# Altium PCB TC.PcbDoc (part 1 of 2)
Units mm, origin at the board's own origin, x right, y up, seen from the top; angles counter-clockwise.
Board outline 53.6 x 100 mm, 2 copper layers (Top Layer, Bottom Layer), stack 1.554 mm thick; 127 components, 95 nets, 328 pads, 171 vias.
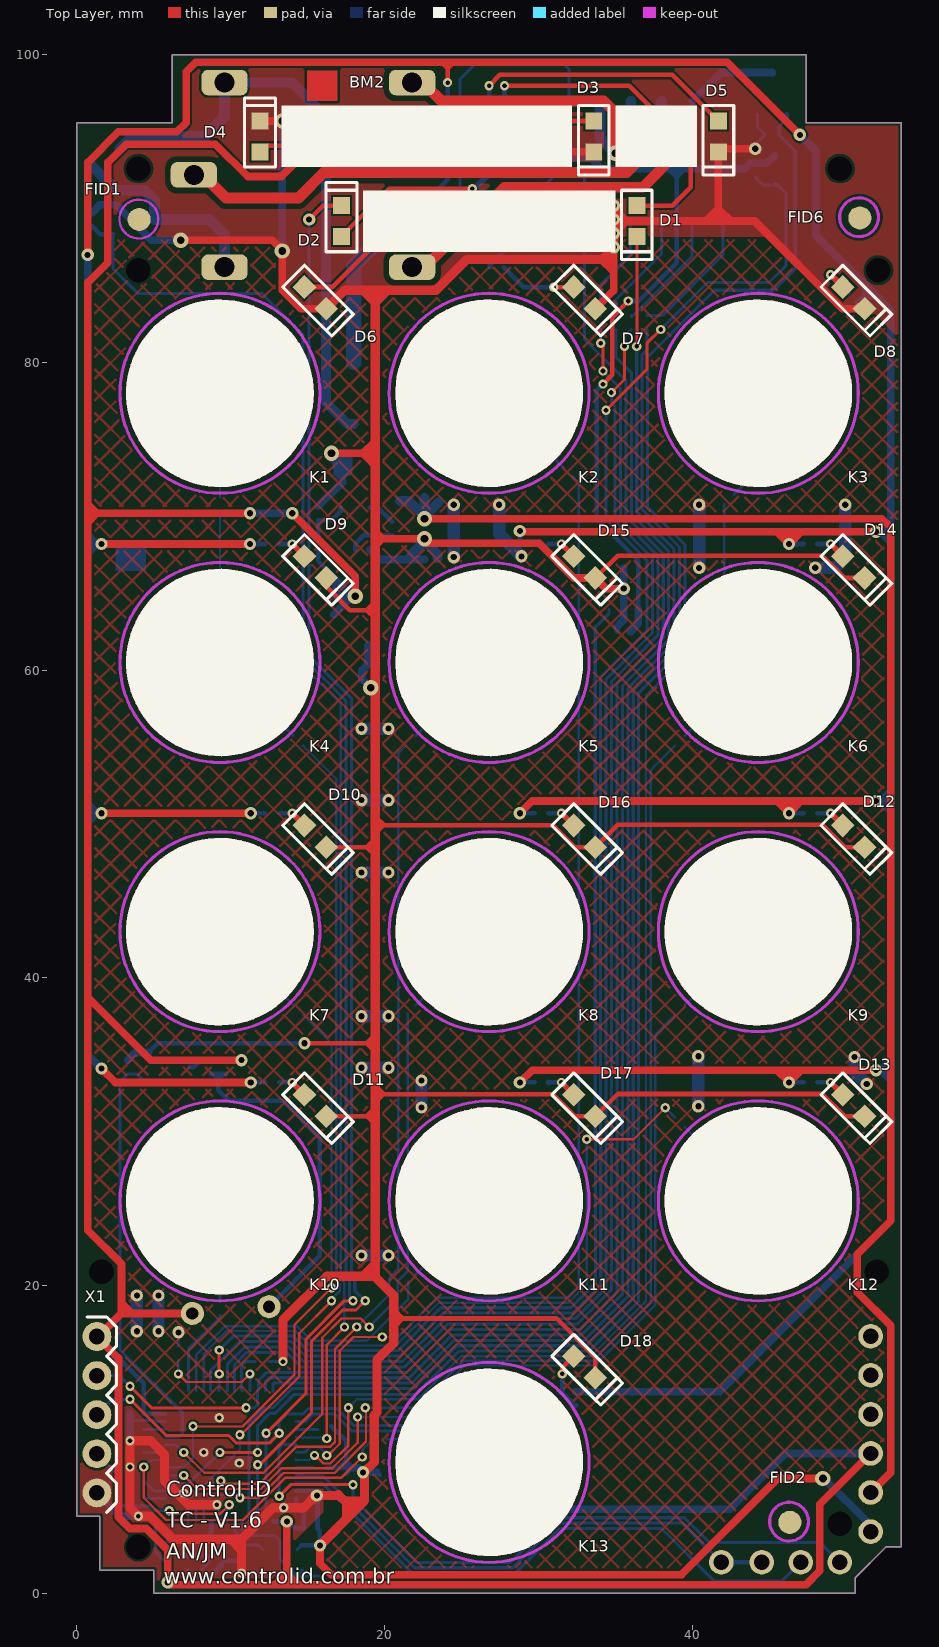
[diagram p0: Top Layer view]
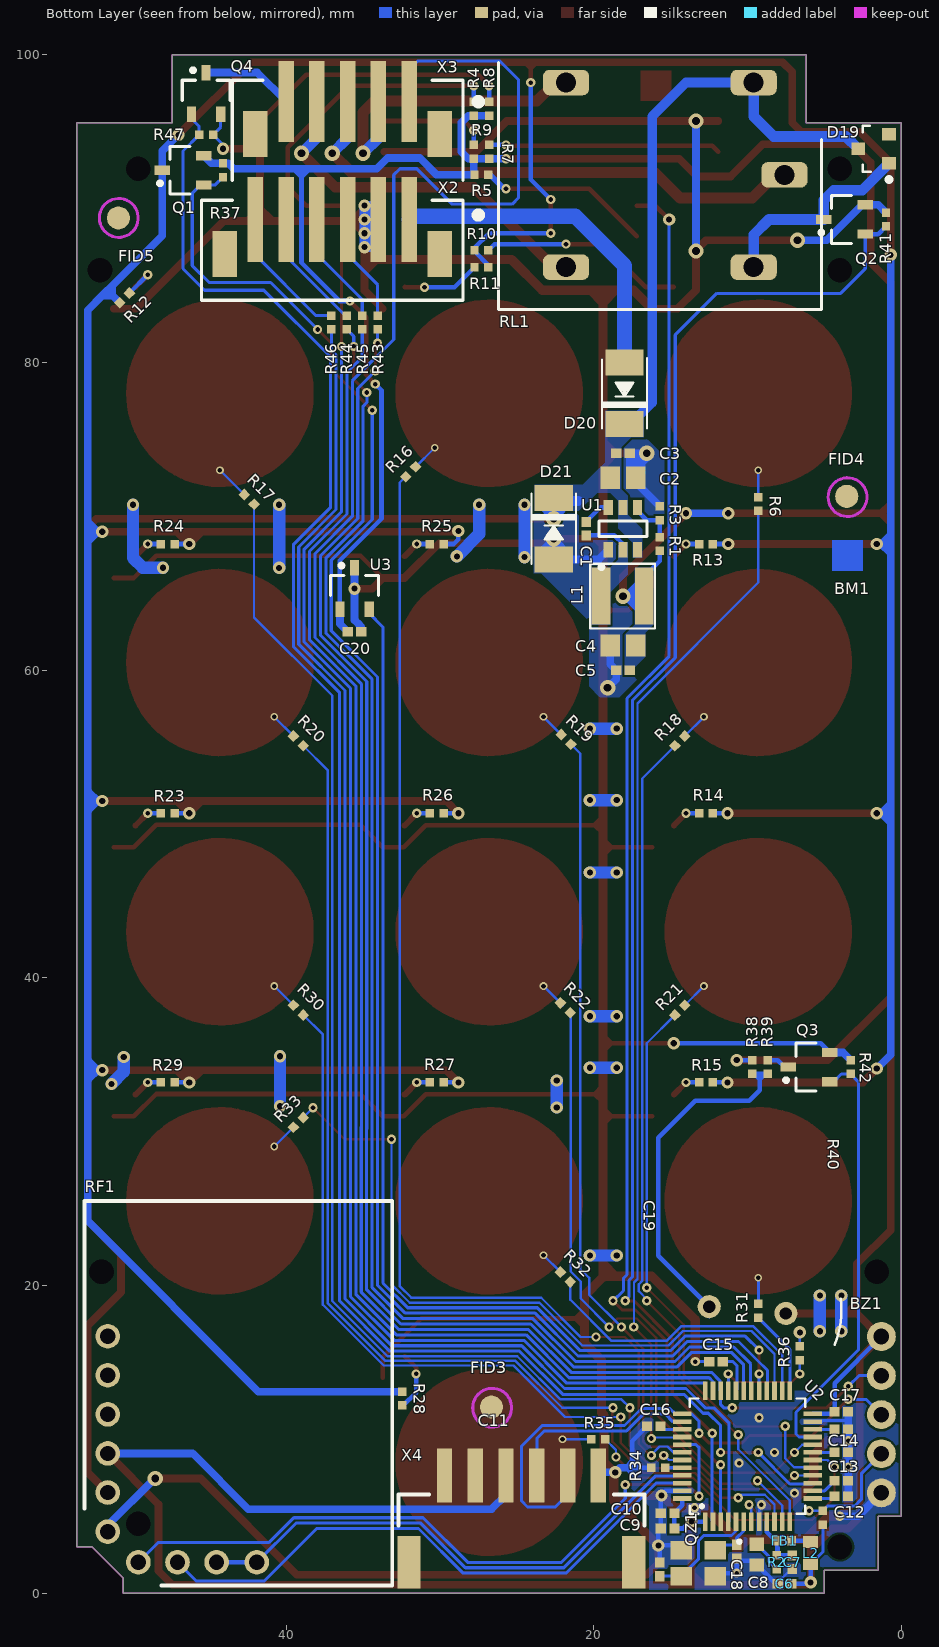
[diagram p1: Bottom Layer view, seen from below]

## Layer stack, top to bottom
Top Solder: solder mask 0.0102, Solder Resist, Dk 3.5
Top Layer: signal copper 0.0356
Dielectric 1: dielectric 1.4834, FR-4, Dk 4.8
Bottom Layer: signal copper 0.0356
Bottom Solder: solder mask 0.0102, Solder Resist, Dk 3.5

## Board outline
1.5,1.5 5,1.5 5,0 50.6,0 50.6,1 52.6,3 53.6,3 53.6,95.6 47.4,95.6 47.4,100 6.2,100 6.2,95.6 0,95.6 0,5 1.5,5

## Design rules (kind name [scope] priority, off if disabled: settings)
BoardOutlineClearance BoardOutlineClearance_1 [OnLayer('Top Overlay') or  OnLayer('Bottom Overlay')] p1: gap=0.051 ignorepadtopadclearanceinfootprint=FALSE
BoardOutlineClearance X1C [InComponent('X1')] p2 off: gap=0.102 ignorepadtopadclearanceinfootprint=FALSE
BoardOutlineClearance [All] p3: gap=0.152 ignorepadtopadclearanceinfootprint=FALSE
Clearance RELAY [InNet('COM_1') or InNet('NO_1') or InNet('NC_1')] p1: gap=0.254 ignorepadtopadclearanceinfootprint=FALSE except(0: Arc-Hole Track-Hole SMDPad-Hole THPad-Hole Via-Hole Fill-Hole Poly-Hole Region-Hole Text-Hole; 0.381: Arc-Poly Track-Poly SMDPad-Poly THPad-Poly Via-Poly Fill-Poly Poly-Poly)
Clearance X1 [InComponent('X1') vs OnLayer('Keep-Out Layer')] p2 off: gap=0.152 ignorepadtopadclearanceinfootprint=FALSE except(0: Arc-Hole Track-Hole SMDPad-Hole THPad-Hole Via-Hole Fill-Hole Poly-Hole Region-Hole Text-Hole)
Clearance U1Clear [InComponent('U1')] p3: gap=0.152 ignorepadtopadclearanceinfootprint=FALSE except(0: Arc-Hole Track-Hole SMDPad-Hole THPad-Hole Via-Hole Fill-Hole Poly-Hole Region-Hole Text-Hole)
Clearance [All] p4: gap=0.152 ignorepadtopadclearanceinfootprint=FALSE except(0: Arc-Hole Track-Hole SMDPad-Hole THPad-Hole Via-Hole Fill-Hole Poly-Hole Region-Hole Text-Hole)
ComponentClearance ComponentClearance_1 [HasFootprint('CAPKEY - NEW') vs HasFootprint('LTST-S270TBKT')] p1: gap=0 collisioncheckmode=3 verticalgap=0 showdistances=TRUE
ComponentClearance BZ1 [InComponent('BZ1')] p2: gap=0 collisioncheckmode=3 verticalgap=0 showdistances=TRUE
ComponentClearance [All] p3: gap=0.254 collisioncheckmode=3 verticalgap=0.254 showdistances=FALSE
MinimumSolderMaskSliver U1 [InComponent('U1')] p1: minsoldermaskwidth=0.025
MinimumSolderMaskSliver [All] p2: minsoldermaskwidth=0.064
PolygonConnect [All] p1: connectstyle=Direct reliefconductorwidth=0.254 reliefentries=4 polygonreliefangle="90 Angle" airgapwidth=0.254
RoutingVias [All] p1: holewidth=0.4 width=0.8 viastyle="Through Hole" minholewidth=0.3 minwidth=0.6 maxholewidth=0.5 maxwidth=1
SilkToSilkClearance [All] p1: silktosilkclearance=0.025
SilkToSolderMaskClearance [IsPad] p1: minsilkscreentomaskgap=0.025 clearancetoexposedcopper=TRUE
SolderMaskExpansion [All] p1: expansion=0.102
Width [All] p1: maxlimit=1 minlimit=0.152 preferedwidth=0.8 minimp=50.000000 maximp=50.000000 favimp=50.000000
26 further rules are at their usual default settings.

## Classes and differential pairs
net class GROUP3: CAP_GROUP3_1 M_CAPKEY13_1
net class GROUP6: CAP_GROUP6_1
net class Line1: M_CAPKEY1_1 M_CAPKEY2_1 M_CAPKEY3_1
net class Line2: M_CAPKEY4_1 M_CAPKEY5_1 M_CAPKEY6_1
net class Line3: M_CAPKEY7_1 M_CAPKEY8_1 M_CAPKEY9_1
net class Line4: M_CAPKEY10_1 M_CAPKEY11_1 M_CAPKEY12_1
net class Line5: M_CAPKEY13_1

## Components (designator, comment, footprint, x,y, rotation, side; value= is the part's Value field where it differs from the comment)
BM1 "BADMARK" BADMARK 3.5,67.45 r180 bottom
BM2 "BADMARK" BADMARK 15.95,98 r0 top
BZ1 "Buzzer" Buzzer 10,18.4 r5 bottom locked
C1 "Cap0402" C0402 20.5,69.2 r90 bottom value=100n
C2 "Cap0805" C0805 18.1,72.5 r0 bottom value=10u
C3 "Cap0402" C0402 18.1,74.1 r0 bottom value=100n
C4 "Cap0805" C0805 18.1,61.6 r0 bottom value=10u
C5 "Cap0402" C0402 18.1,60 r180 bottom value=100n
C6 "Cap0402" C0402 7.6,0.6 r180 bottom value=100n
C7 "Cap0402" C0402 7.1,2 r90 bottom value=100n
C8 "Cap0603" C0603 9.4,2.5 r90 bottom value=4.7u
C9 "Cap0402" C0402 15.2,4.2 r180 bottom value=100n
C10 "Cap0402" C0402 15.2,5.2 r180 bottom value=100n
C11 "Cap0402" C0402 3.9,11.8 r0 bottom value=100n
C12 "Cap0402" C0402 3.9,6.3 r0 bottom value=22n
C13 "Cap0402" C0402 3.9,7.3 r0 bottom value=22n
C14 "Cap0402" C0402 3.9,9.15 r0 bottom value=22n
C15 "Cap0402" C0402 12.05,15.05 r180 bottom value=22n
C16 "Cap0402" C0402 16.1,10.85 r180 bottom value=22n
C17 "Cap0402" C0402 3.9,10.65 r0 bottom value=10n
C18 "Cap0402" C0402 10.7,2.7 r90 bottom value=18pF
C19 "Cap0402" C0402 15.7,1.54 r270 bottom value=18pF
C20 "Cap0402" C0402 35.55,62.5 r0 bottom value=100n
D1 "XZMDK87W" LTST-S270TBKT 36.4,89.2 r0 top locked
D2 "XZDGK87W" LTST-S270TBKT 17.2,89.2 r180 top locked
D3 "XZCWD87F" LTST-S270TBKT 33.6,94.7 r0 top locked
D4 "XZCWD87F" LTST-S270TBKT 11.9,94.7 r180 top locked
D5 "XZMDK87W" LTST-S270TBKT 41.7,94.7 r0 top locked
D6 "XZCBD87W" LTST-S270TBKT 15.5,84.2 r45 top locked
D7 "XZCBD87W" LTST-S270TBKT 33,84.2 r45 top locked
D8 "XZCBD87W" LTST-S270TBKT 50.5,84.2 r45 top locked
D9 "XZCBD87W" LTST-S270TBKT 15.5,66.7 r45 top locked
D10 "XZCBD87W" LTST-S270TBKT 15.5,49.2 r45 top locked
D11 "XZCBD87W" LTST-S270TBKT 15.5,31.7 r45 top locked
D12 "XZCBD87W" LTST-S270TBKT 50.5,49.2 r45 top locked
D13 "XZCBD87W" LTST-S270TBKT 50.5,31.7 r45 top locked
D14 "XZCBD87W" LTST-S270TBKT 50.5,66.7 r45 top locked
D15 "XZCBD87W" LTST-S270TBKT 33,66.7 r45 top locked
D16 "XZCBD87W" LTST-S270TBKT 33,49.2 r45 top locked
D17 "XZCBD87W" LTST-S270TBKT 33,31.7 r45 top locked
D18 "XZCBD87W" LTST-S270TBKT 33,14.7 r45 top locked
D19 "BAS16LT3G" BAS16LT3G 1.8,93.9 r90 bottom
D20 "B360A-13-F" SMA 18,78 r90 bottom
D21 "SMAJ14A" SMA 22.6,69.2 r270 bottom
FB1 "Ferrite Bead" FB0402 7.6,3.4 r0 bottom
FID1 "FIDUCIAL" FIDUCIAL-1p5X3 4.05,89.3 r0 top
FID2 "FIDUCIAL" FIDUCIAL-1p5X3 46.35,4.6 r90 top
FID3 "FIDUCIAL" FIDUCIAL-1p5X3 26.65,12.1 r90 bottom
FID4 "FIDUCIAL" FIDUCIAL-1p5X3 3.55,71.3 r90 bottom
FID5 "FIDUCIAL" FIDUCIAL-1p5X3 50.9,89.4 r90 bottom
FID6 "FIDUCIAL" FIDUCIAL-1p5X3 50.9,89.4 r90 top
K1 "CAP_KEY" "CAPKEY - NEW" 9.3,78 r90 top locked
K2 "CAP_KEY" "CAPKEY - NEW" 26.8,78 r135 top locked
K3 "CAP_KEY" "CAPKEY - NEW" 44.3,78 r90 top locked
K4 "CAP_KEY" "CAPKEY - NEW" 9.3,60.5 r135 top locked
K5 "CAP_KEY" "CAPKEY - NEW" 26.8,60.5 r45 top locked
K6 "CAP_KEY" "CAPKEY - NEW" 44.3,60.5 r45 top locked
K7 "CAP_KEY" "CAPKEY - NEW" 9.3,43 r135 top locked
K8 "CAP_KEY" "CAPKEY - NEW" 26.8,43 r45 top locked
K9 "CAP_KEY" "CAPKEY - NEW" 44.3,43 r45 top locked
K10 "CAP_KEY" "CAPKEY - NEW" 9.3,25.5 r90 top locked
K11 "CAP_KEY" "CAPKEY - NEW" 26.8,25.5 r45 top locked
K12 "CAP_KEY" "CAPKEY - NEW" 44.3,25.5 r315 top
K13 "CAP_KEY" "CAPKEY - NEW" 26.8,8.5 r342.5 top locked
L1 "Inductor" NRS4018T3R3MDGJ 18.1,64.8 r180 bottom value=3.3u
L2 "Inductor" L0603 5.9,2.6 r90 bottom value=10u
Q1 "MOSFET-P" SOT23-3 46.7,92.5 r0 bottom
Q2 "DMN3404" SOT23-3 3.7,89.3 r0 bottom
Q3 "DMN3404" SOT23-3 6,34.2 r0 bottom
Q4 "DMN3404" SOT23-3 45.2,97.5 r90 bottom
QZ1 "ABM8G-12.000MHZ-18-D2Y-T" ABM8G-12.000MHZ-18-D2Y-T 13.2,1.95 r180 bottom locked value=12.000MHZ
R1 "Res0402" R0402 15.7,68.2 r270 bottom value=33K
R2 "Res0402" R0402 8.1,2 r90 bottom value=1
R3 "Res0402" R0402 15.7,70.2 r270 bottom value=10K
R4 "Res0402" R0402 27.8,96.5 r90 bottom value=68
R5 "Res0402" R0402 27.3,92.2 r180 bottom value=10
R6 "Res0402" R0402 9.3,70.8 r90 bottom value=10K
R7 "Res0402" R0402 26.8,93.7 r270 bottom value=10
R8 "Res0402" R0402 26.8,96.5 r270 bottom value=68
R9 "Res0402" R0402 27.8,93.7 r270 bottom value=10
R10 "Res0402" R0402 27.3,87.3 r0 bottom value=10
R11 "Res0402" R0402 27.3,86.2 r180 bottom value=10
R12 "Res0402" R0402 50.5,84.2 r315 bottom value=10
R13 "Res0402" R0402 12.7,68.2 r180 bottom value=10
R14 "Res0402" R0402 12.7,50.7 r180 bottom value=10
R15 "Res0402" R0402 12.7,33.2 r180 bottom value=10
R16 "Res0402" R0402 31.9,72.9 r135 bottom value=10K
R17 "Res0402" R0402 42.4,71.1 r45 bottom value=10K
R18 "Res0402" R0402 14.4,55.4 r135 bottom value=10K
R19 "Res0402" R0402 21.8,55.5 r45 bottom value=10K
R20 "Res0402" R0402 39.2,55.4 r45 bottom value=10K
R21 "Res0402" R0402 14.4,37.9 r135 bottom value=10K
R22 "Res0402" R0402 21.85,38.05 r45 bottom value=10K
R23 "Res0402" R0402 47.7,50.7 r180 bottom value=10
R24 "Res0402" R0402 47.7,68.2 r180 bottom value=10
R25 "Res0402" R0402 30.2,68.2 r180 bottom value=10
R26 "Res0402" R0402 30.2,50.7 r180 bottom value=10
R27 "Res0402" R0402 30.2,33.2 r180 bottom value=10
R28 "Res0402" R0402 32.45,12.65 r90 bottom value=10
R29 "Res0402" R0402 47.7,33.2 r180 bottom value=10
R30 "Res0402" R0402 39.2,37.9 r45 bottom value=10K
R31 "Res0402" R0402 9.3,18.35 r90 bottom value=10K
R32 "Res0402" R0402 21.85,20.55 r45 bottom value=10K
R33 "Res0402" R0402 39.2,30.6 r315 bottom value=10K
R34 "Res0402" R0402 15.8,8.15 r0 bottom value=1K
R35 "Res0402" R0402 19.7,10 r0 bottom value=10K
R36 "Res0402" R0402 6.6,15.6 r90 bottom value=10K
R37 "Res0402" R0402 44.1,92.5 r90 bottom value=1K
R38 "Res0402" R0402 9.7,34.2 r90 bottom value=1K
R39 "Res0402" R0402 8.7,34.2 r270 bottom value=27
R40 "Res0402" R0402 5.1,4.9 r270 bottom value=10K
R41 "Res0402" R0402 1,89.3 r270 bottom value=1K
R42 "Res0402" R0402 3.3,34.2 r90 bottom value=1K
R43 "Res0402" R0402 34.05,82.6 r90 bottom value=1K
R44 "Res0402" R0402 36.05,82.6 r90 bottom value=1K
R45 "Res0402" R0402 35.05,82.6 r90 bottom value=1K
R46 "Res0402" R0402 37.05,82.6 r90 bottom value=1K
R47 "Res0402" R0402 45.2,94.8 r180 bottom value=1K
RF1 "REPASK/REPMIF" REPASK_REPMIF 53.1,25.5 r270 bottom locked
RL1 "HK3FF" HK3FF 15.7,92.2 r180 bottom locked
U1 "TPS562209DDCR" SOT6 18.1,69.2 r90 bottom
U2 "STM32F051C8T6" LQFP48 10,8.9 r180 bottom locked
U3 "S-5712ACDH1-M3T1U" SOT23-3 35.55,65.3 r90 bottom locked
X1 "Header 5" 1X05 1.3,11.6 r270 top locked
X2 "JST6_VERT" JST6_VERT 37,87.3 r180 bottom locked
X3 "JST5_VERT" JST5_VERT 36,95.1 r180 bottom locked
X4 "JST6_HORIZ" JST6_HORIZ 24.7,0.4 r0 bottom locked

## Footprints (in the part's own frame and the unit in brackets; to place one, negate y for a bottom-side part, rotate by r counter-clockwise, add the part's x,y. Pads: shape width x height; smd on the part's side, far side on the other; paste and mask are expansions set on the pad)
1X05 [mil]
  round 74 hole 40: 1(-200,0) 2(-100,0) 3(0,0) 4(100,0) 5(200,0)
  silkscreen extent -250,-25 250,50
ABM8G-12.000MHZ-18-D2Y-T [mm]
  rect 1.4x1.2 smd: 1(1.1,0.85) 2(-1.1,0.85) 3(-1.1,-0.85) 4(1.1,-0.85)
  silkscreen extent 2.56,1.29 2.77,1.5, body extent -1.6,-1.25 1.6,1.25, height 1
BADMARK [mm]
  Top Layer region: -1,1 1,1 1,-1 -1,-1
BAS16LT3G [mm]
  rect 0.8x0.9 smd mask+0.051: 1(-0.95,-1) 2(0.95,-1) 3(0,1)
  silkscreen extent -2.04,-1.04 1.5,0.7, body extent -1.45,-0.65 1.45,0.65, height 1.21
Buzzer [mil]
  round 59.06 hole 31.5: 1(-98.43,0) 2(98.43,0)
  silkscreen extent -240,-50 -230,69, body extent -240,-240 240,240, height 268
C0402 [mm] "Chip Capacitor, 2-Leads, Body 1,00x0,50mm, IPC Medium Density"
  rect 0.66x0.62 smd mask+0.051: 1(-0.44,0) 2(0.44,0)
  body extent -0.53,-0.28 0.53,0.28, height 0.55
C0603 [mm] "Chip Capacitor, 2-Leads, Body 1,60x0,80mm, IPC Medium Density"
  rect 0.85x0.95 smd: 1(-0.675,0) 2(0.675,0)
  body extent -0.85,-0.45 0.85,0.45, height 0.9
C0805 [mm] "Chip Capacitor, 2-Leads, Body 2,00x1,25mm, IPC Medium Density"
  rect 1.25x1.45 smd: 1(-0.825,0) 2(0.825,0)
  body extent -1.1,-0.72 1.1,0.73, height 1.25
"CAPKEY - NEW" [mm]
  round 1.5 smd paste-5 mask-2540: 1(0,0)
  Top Layer circle w0.203: c0,0 r6
  Top Layer region: 0,-6 -2.296,-5.543 -4.243,-4.243 -5.543,-2.296 -6,0 -6,0 -5.543,2.296 -4.243,4.243 -2.296,5.543 0,6 0,6 2.296,5.543 4.243,4.243 5.543,2.296 6,0 6,0 5.543,-2.296 4.243,-4.243 2.296,-5.543 0,-6
  silkscreen extent -6,-6 6,6
FB0402 [mm]
  rect 0.59x0.62 smd: 1(-0.455,0) 2(0.455,0)
  body extent -0.53,-0.28 0.53,0.27, height 0.5
FIDUCIAL-1p5X3 [mm]
  rrect100% 1.5x1.5 smd: 1(0,0)
HK3FF [mm]
  rrect50% 3x1.65 hole 1.3: 1(6.1,6) 2(8.1,0) 3(-6.1,6) 4(-6.1,-6) 5(6.1,-6)
  silkscreen extent -10.5,-8.75 10.5,7.3, body extent -9.5,-7.75 9.5,7.75, height 15.8
JST5_VERT [mm]
  rect 1x5.25 smd paste+0: 1(4,1.875) 2(2,1.875) 3(0,1.875) 4(-2,1.875) 5(-4,1.875)
  rect 1.6x3 smd: P1(6,-0.25) P2(-6,-0.25)
  silkscreen extent -7.5,-3.25 8.68,3.25, body extent -7,-2.75 7,2.75, height 6
JST6_HORIZ [mm] "SMT Horizontal JST 6 leads connector"
  rect 1x3.5 smd: 1(-5,-7.25) 2(-3,-7.25) 3(-1,-7.25) 4(1,-7.25) 5(3,-7.25) 6(5,-7.25)
  rect 1.5x3.4 smd: P1(-7.3,-1.6) P2(7.3,-1.6)
  silkscreen extent -8,-6 8,-4, body extent -7.95,-8.6 7.95,0, height 5.5
JST6_VERT [mm]
  rect 1x5.5 smd: 1(5,2) 2(3,2) 3(1,2) 4(-1,2) 5(-3,2) 6(-5,2)
  rect 1.6x3 smd: P1(7,-0.25) P2(-7,-0.25)
  silkscreen extent -8.5,-3.25 9.68,3.25, body extent -8,-2.75 8,4.75, height 6.01
L0603 [mm]
  rect 0.77x0.98 smd: 1(-0.715,0) 2(0.715,0)
  body extent -0.88,-0.48 0.87,0.47, height 0.8
LQFP48 [mm]
  rect 0.3x1.2 smd mask+0.051: 1(-2.75,-4.25) 2(-2.25,-4.25) 3(-1.75,-4.25) 4(-1.25,-4.25) 5(-0.75,-4.25) 6(-0.25,-4.25) 7(0.25,-4.25) 8(0.75,-4.25) 9(1.25,-4.25) 10(1.75,-4.25) 11(2.25,-4.25) 12(2.75,-4.25) 25(2.75,4.25) 26(2.25,4.25) 27(1.75,4.25) 28(1.25,4.25) 29(0.75,4.25) 30(0.25,4.25) 31(-0.25,4.25) 32(-0.75,4.25) 33(-1.25,4.25) 34(-1.75,4.25) 35(-2.25,4.25) 36(-2.75,4.25)
  rect 1.2x0.3 smd mask+0.051: 13(4.25,-2.75) 14(4.25,-2.25) 15(4.25,-1.75) 16(4.25,-1.25) 17(4.25,-0.75) 18(4.25,-0.25) 19(4.25,0.25) 20(4.25,0.75) 21(4.25,1.25) 22(4.25,1.75) 23(4.25,2.25) 24(4.25,2.75) 37(-4.25,2.75) 38(-4.25,2.25) 39(-4.25,1.75) 40(-4.25,1.25) 41(-4.25,0.75) 42(-4.25,0.25) 43(-4.25,-0.25) 44(-4.25,-0.75) 45(-4.25,-1.25) 46(-4.25,-1.75) 47(-4.25,-2.25) 48(-4.25,-2.75)
  silkscreen extent -3.75,-3.75 3.75,3.75, body extent -3.5,-3.5 3.5,3.5, height 1.6
LTST-S270TBKT [mm]
  rect 1.1x1.1 smd: 1(0,1) 2(0,-1)
  silkscreen extent -1,-2.5 1,2, body extent -0.81,-0.82 0.34,0.82, height 0.6
NRS4018T3R3MDGJ [mm]
  rect 1.2x3.7 smd mask+0.064: 1(-1.422,0.01) 2(1.378,0.01)
  silkscreen extent -2.12,-2.09 2.08,2.11
R0402 [mm] "Chip Resistor, 2-Leads, Body 1,00x0,50mm, IPC Medium Density"
  rect 0.55x0.55 smd: 1(-0.45,0) 2(0.45,0)
  body extent -0.53,-0.28 0.53,0.28, height 0.45
REPASK_REPMIF [mm]
  round 1.6 hole 1: 1(18.96,1.5) 2(16.42,1.5) 3(23.5,3.5) 4(23.5,6.04) 5(23.5,8.58) 6(23.5,11.2) 7(13.88,1.5) 8(11.34,1.5) 9(8.8,1.5) 10(21.5,1.5)
  silkscreen extent 0,0 25,20, body extent 0,0 25,20, height 10
SMA [mm]
  rect 1.7x2.5 smd: 1(2,0) 2(-2,0)
  silkscreen extent -2.3,-1.46 2.3,1.46, body extent -2.5,-1.35 2.5,1.35, height 2.15
SOT6 [mm] "SOT23, 6-Leads, Body 2,90x2,80mm, Pitch 0,95mm, IPC Medium Density"
  rect 1x0.6 smd: 1(-1.375,0.95) 2(-1.375,0) 3(-1.375,-0.95) 4(1.375,-0.95) 5(1.375,0) 6(1.375,0.95)
  silkscreen extent -2.62,-1.55 0.5,1.55, body extent -0.88,-1.52 0.88,1.52, height 1.1
SOT23-3 [mm]
  rect 1x0.6 smd: 1(1.35,0) 2(-1.35,0.95) 3(-1.35,-0.95)
  silkscreen extent -0.45,-1.55 1.63,1.55, body extent -1.25,-1.5 1.25,1.5, height 1.1

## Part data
BM1 BM2: "Bad Mark Indicator"
BZ1: "Standard PTH Buzzer"
C1 C2 C3 C4 C5 C6 C7 C8 C9 C10 C11 C18 C19 C20: "Capacitor", Tolerance=10%
C12 C13 C14 C15 C16 C17: "Capacitor", Tolerance=1%
D1 D2 D3 D4 D5 D6 D7 D8 D9 D10 D11 D12 D13 D14 D15 D16 D17 D18: library part LTST-S270TBKT, "Light-Emitting Diode (side-emitting)"
D19: "DIODE GEN PURP 75V 200MA SOT23-3", Capacitance @ Vr, F="2pF @ 0V, 1MHz", Current - Average Rectified (Io)="200mA (DC)", Current - Reverse Leakage @ Vr="1µA @ 75V", Manufacturer="ON Semiconductor", Operating Temperature - Junction="-55°C ~ 150°C", Package / Case="TO-236-3, SC-59, SOT-23-3", Supplier Device Package="SOT-23-3 (TO-236)", Supplier Part Number 1=BAS16LT3GOSTR-ND, Voltage - DC Reverse (Vr) (Max)=75V, Voltage - Forward (Vf) (Max) @ If="1.25V @ 150mA"
D20: library part B360A, "B360A Diode", Capacitance @ Vr, F="200pF @ 4V, 1MHz", Current - Average Rectified (Io)=3A, Current - Reverse Leakage @ Vr="500µA @ 60V", Manufacturer="Diodes Incorporated", Operating Temperature - Junction="-55°C ~ 150°C", Package / Case="DO-214AC, SMA", Supplier Device Package=SMA, Supplier Part Number 1=B360A-FDICT-ND, Voltage - DC Reverse (Vr) (Max)=60V, Voltage - Forward (Vf) (Max) @ If="700mV @ 3A"
D21: "TVS DIODE 14VWM 23.2VC SMA", Capacitance @ Frequency=-, Current - Peak Pulse (10/1000µs)=17.2A, Manufacturer="Littelfuse Inc.", Operating Temperature="-55°C ~ 150°C (TJ)", Package / Case="DO-214AC, SMA", Power - Peak Pulse=400W, Power Line Protection=No, Supplier Device Package="DO-214AC (SMA)", Supplier Part Number 1=SMAJ14ALFCT-ND, Voltage - Breakdown (Min)=15.6V, Voltage - Clamping (Max) @ Ipp=23.2V, Voltage - Reverse Standoff (Typ)=14V
FID1 FID2 FID3 FID4 FID5 FID6: "Standard fiducial for Control iD boards"
L1: Part number=NRS4018T3R3MDGJ
Q1: "P-Channel MOSFET"
Q2 Q3 Q4: "DMN3404 N-Channel MOSFET", Supplier Part Number 1=DMN3404LDICT-ND
R1 R2 R3 R4 R5 R6 R7 R8 R9 R10 R11 R12 R13 R14 R15 R16 R17 R18 R19 R20 R21 R22 R23 R24 R25 R26 R27 R28 R29 R30 R31 R32 R33 R34 R35 R36 R37 R38 R39 R40 R41 R42 R43 R44 R45 R46 R47: "Resistor", Tolerance=5%
RF1: "Control iD RF Module"
RL1: "SPDT Relay HK3FF"
U3: "Hall effect sensor from Seiko"
X1: "Header, 5-Pin, Single row, 0.1\""
X2 X4: "Header, 6-Pin"
X3: "Header, 5-Pin"

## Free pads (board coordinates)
  round 0 hole 1.6: 0(1.6,20.9) 0(4,3) 0(4,86) 0(4,92.6) 0(49.6,4.5) 0(49.6,92.6) 0(52,20.9) 0(52.1,86)

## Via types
v1: diameter 0.6, hole 0.3, Top Layer to Bottom Layer, tented both sides, 82 vias
v2: diameter 0.8, hole 0.4, Top Layer to Bottom Layer, tented both sides, 64 vias
v3: diameter 0.5, hole 0.3, Top Layer to Bottom Layer, tented both sides, 13 vias
v4: diameter 1, hole 0.5, Top Layer to Bottom Layer, tented both sides, 12 vias

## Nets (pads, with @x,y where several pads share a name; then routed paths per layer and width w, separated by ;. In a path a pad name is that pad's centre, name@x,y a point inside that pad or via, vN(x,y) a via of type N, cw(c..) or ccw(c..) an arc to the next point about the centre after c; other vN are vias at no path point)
+3V3: BZ1.1 C4.1 C5.2 C6.2 C9.2 C10.2 C11.2 C20.2 L1.2 L2.1 Q1.3 R1.2 R4.1 R5.1 R7.2 R8.2 R9.2 R37.2 R38.2 R40.2 RF1.2 U2.1 U2.24 U2.48 U3.2 X1.1 X4.4 | length 339
  Top Layer w0.152: X1.1@1.3,16.68 X1.1@1.398,16.68 ; BZ1.1@7.22,18.28 7.318,18.182 BZ1.1@7.5,18
  Top Layer w0.3: v1(34.2,78.6) 34.802,79.2 34.802,79.7 34.8,79.702 34.8,82.95 v1(35.85,84)
  Top Layer w0.5: X1.1@1.3,16.68 2.7,15.28 2.7,4.95 3.448,4.202 4.498,4.202 5.9,2.8 v2(5.9,0.7) 6.05,0.55 13.65,0.55 ; X1.1@1.398,16.68 2.9,18.182 ; BZ1.1@7.509,18.182 7.318,18.182 3.55,18.182 ; v2(10.7,34.65) 4.8,34.65 0.7,38.75 ; v2(11.25,70.2) 11.4,70.2 1.3,70.2 ; 12.9,0.55 13.65,1.3 ; v2(13.65,4.65) 13.65,1.3 ; v2(14,70.2) 18.1,66.1 v4(18.1,64.8) ; v1(25.7,93.25) 14.45,93.25 13.3,92.1 11.1,92.1 9,94.2 3.2,94.2 2,93 2,86.5 0.7,85.2 0.7,70.8 ; RF1.2@51.6,9.08 48.3,5.78 48.3,1.45 47.4,0.55 14.4,0.55 ; 0.7,38.75 0.7,23.6 2.9,21.4 2.9,18.832 ; 0.7,38.75 0.7,69.6 ; 0.7,69.6 1.3,70.2 ; 0.7,69.6 0.7,70.8 ; 0.7,70.8 1.3,70.2 ; 2.9,18.182 2.9,18.832 ; 2.9,18.182 3.55,18.182 ; 2.9,18.832 3.55,18.182 ; 13.65,0.55 14.4,0.55 ; 13.65,0.55 13.65,1.3 ; 13.65,1.3 14.4,0.55
  Bottom Layer w0.152: v2(13.65,4.65) v2@13.7,4.7
  Bottom Layer w0.2: R40.2@5.1,4.45 5.1,2.685 L2.1@5.9,1.885 ; v2(5.9,0.7) 6,0.6 v2@6.1,0.6 ; U2.1@12.75,4.65 12.85,4.65 v2(13.65,4.65) ; X4.4@25.7,6.4 X4.4@25.7,7.65
  Bottom Layer w0.3: X1.1@1.3,16.68 4.34,13.64 C11.2@4.34,11.8 4.34,11.65 U2.24@5.75,11.65 ; v2(5.9,0.7) L2.1@5.9,1.885 L2.1@5.9,1.985 ; v2@6.1,0.6 C6.2@7.16,0.6 ; R38.2@9.7,34.65 v2(10.7,34.65) ; U2.1@12.8,4.7 12.85,4.65 v2(13.65,4.65) ; v2@13.7,4.7 14.2,4.2 C9.2@14.76,4.2 C10.2@14.76,5.2 14.25,5.71 U2.48@14.25,6.15 ; R1.2@15.7,67.75 15.7,67.1 16.722,66.078 16.722,65.978 L1.2@16.722,64.81 ; v1(34.2,78.6) 33.798,78.198 33.798,69.833 36.5,67.131 U3.2@36.5,63.95 ; v1(35.85,84) 36.524,84 39,86.476 39,92.05 ; 38.454,92.596 39,92.05 ; 39,92.596 39,92.05 ; 39.55,92.596 39.546,92.596 39,92.05
  Bottom Layer w0.5: v2(11.25,70.2) v2(14,70.2) ; L1.2@16.7,63.6 v4@17.9,64.8 ; L1.2@16.7,66 16.722,65.978 v4@17.89,64.81 ; L1.2@16.722,64.81 v4@17.89,64.81 ; X4.4@25.7,6.4 26.65,5.45 42.45,5.45 46.08,9.08 RF1.2@51.6,9.08 ; v1(25.7,93.25) R7.2@26.8,93.25 R9.2@27.8,93.25 ; R8.2@26.8,96.05 R4.1@27.8,96.05 28.15,96.05 28.6,95.6 28.6,93.7 28.15,93.25 R9.2@27.8,93.25 ; C20.2@35.99,62.5 36.5,63.01 U3.2@36.5,63.95 ; 39.546,92.596 39,92.596 38.454,92.596 34.104,92.596 33.4,93.3 31.319,93.3 30.219,92.2 27.8,92.2 R9.2@27.8,93.25 ; 39.55,92.596 43.396,92.596 43.75,92.95 R37.2@44.1,92.95 44.85,92.95 Q1.3@45.35,93.45 ; v4@17.89,64.81 v4@17.9,64.8 ; v4@17.89,64.81 18.09,64.81 v4(18.1,64.8) v4@17.9,64.8
+3V3_LED: Q1.1 R10.2 R11.2 R12.2 R13.2 R14.2 R15.2 R23.2 R24.2 R25.2 R26.2 R27.2 R28.2 R29.2 | length 363.5
  Top Layer w0.3: v1(22.8,88.4) v1(22.8,90.6) ; 23.6,99.529 23.7,99.529 24.1,99.129 ; v1(24.1,98.2) 24.1,99.129 ; 24.1,99.529 24.1,99.129 ; 24.5,99.529 24.1,99.129
  Top Layer w0.5: v2(0.7,87) 0.7,93 2.7,95 6.5,95 7.1,95.6 7.1,98.9 7.729,99.529 23.6,99.529 ; v2(1.6,34.1) 2.5,33.2 v2(11.3,33.2) ; v2(1.6,50.7) v2(11.3,50.7) ; v2(1.6,68.2) v2(11.25,68.2) ; 23.7,99.529 24.1,99.529 24.5,99.529 42.271,99.529 v2(47,94.8) ; v2(28.8,33.2) 29.6,34 45.5,34 ; v2(28.8,50.7) 29.6,51.5 45.5,51.5 ; v2(28.8,69.05) 28.85,69 45.5,69 ; v2(51.95,34) 47.1,34 ; v2(51.95,51.5) 47.1,51.5 ; v2(51.95,69) 47.1,69 ; 45.5,34 46.3,34 ; 45.5,34 v2(46.3,33.2) ; 45.5,51.5 46.3,51.5 ; 45.5,51.5 v2(46.3,50.7) ; 45.5,69 46.3,69 ; 45.5,69 v2(46.3,68.2) ; v2(46.3,33.2) 46.3,34 ; v2(46.3,33.2) 47.1,34 ; 46.3,34 47.1,34 ; v2(46.3,50.7) 46.3,51.5 ; v2(46.3,50.7) 47.1,51.5 ; 46.3,51.5 47.1,51.5 ; v2(46.3,68.2) 46.3,69 ; v2(46.3,68.2) 47.1,69 ; 46.3,69 47.1,69
  Bottom Layer w0.3: v2(11.25,68.2) R13.2@12.25,68.2 ; v2(11.3,33.2) R15.2@12.25,33.2 ; v2(11.3,50.7) R14.2@12.25,50.7 ; v1(22.8,88.4) 26.8,88.4 27.75,87.45 R10.2@27.75,87.3 27.75,87.222 26.85,86.322 R11.2@26.85,86.2 ; v1(22.8,90.6) 24.1,91.9 v1(24.1,98.2) ; v2(28.8,33.2) R27.2@29.75,33.2 ; v2(28.8,50.7) R26.2@29.75,50.7 ; v2(28.8,69.05) 28.8,68.493 29.093,68.2 R25.2@29.75,68.2 ; v2(46.3,33.2) R29.2@47.25,33.2 ; v2(46.3,50.7) R23.2@47.25,50.7 ; v2(46.3,68.2) R24.2@47.25,68.2 ; 52.85,69 52.9,69.05
  Bottom Layer w0.5: v2(0.7,87) 0.7,68.8 ; v2(1.6,34.1) 0.7,35 0.7,50.1 ; v2(1.6,50.7) v2@1.3,50.7 ; v2(1.6,68.2) v2@1.3,68.2 ; R28.2@32.45,13.1 41.8,13.1 52.9,24.2 52.9,69.05 52.9,83.4 51.936,84.364 ; v2(47,94.8) 48.05,93.75 Q1.1@48.05,92.5 48.05,88.25 51.3,85 ; R12.2@50.818,83.882 51.3,84.364 ; 51.6,84.7 51.3,85 ; v2(51.95,34) v2@52.25,34 ; v2(51.95,51.5) v2@52.25,51.5 ; v2(51.95,69) v2@52.25,69 ; 52.85,33.4 v2@52.25,34 ; 52.85,34 v2@52.25,34 ; 52.85,34.6 v2@52.25,34 ; 52.85,50.9 v2@52.25,51.5 ; 52.85,51.5 v2@52.25,51.5 ; 52.85,52.1 v2@52.25,51.5 ; 52.85,68.4 v2@52.25,69 ; 52.85,69 v2@52.25,69 ; 52.85,69.6 v2@52.25,69 ; 0.7,50.1 v2@1.3,50.7 ; 0.7,50.1 0.7,50.7 ; 0.7,50.7 v2@1.3,50.7 ; 0.7,50.7 0.7,51.3 ; 0.7,51.3 v2@1.3,50.7 ; 0.7,51.3 0.7,67.6 ; 0.7,67.6 v2@1.3,68.2 ; 0.7,67.6 0.7,68.2 ; 0.7,68.2 v2@1.3,68.2 ; 0.7,68.2 0.7,68.8 ; 0.7,68.8 v2@1.3,68.2 ; 51.3,84.364 51.3,85 ; 51.3,84.364 51.618,84.682 51.936,84.364 ; 51.3,84.364 51.936,84.364
+3V3A: C7.2 FB1.2 R2.2 U2.9 | length 3.6
  Bottom Layer w0.3: C7.2@7.1,2.44 7.11,2.45 R2.2@8.1,2.45 8.055,2.495 FB1.2@8.055,3.4 8.178,3.4 8.75,3.972 U2.9@8.75,4.65
+12V: C2.2 C3.2 D19.3 D20.2 D21.2 RF1.1 RL1.1 U1.3 U1.5 | length 138.6
  Top Layer w0.5: v4(22.6,69.85) 22.602,69.852 52.332,69.852 52.9,69.285 52.9,24.2 50.73,22.03 50.73,19.57 52.9,17.4 52.9,7.84 RF1.1@51.6,6.54
  Bottom Layer w0.635: RL1.1@9.6,98.2 14,98.2 16.2,96 16.2,77.4 17.6,76 D20.2@18,76 ; 21,71 21.6,71 v4@22.6,70 ; v4(22.6,69.85) v4@22.6,70 ; D21.2@22.6,71.2 v4@22.6,70 ; D21.2@23.5,70.9 v4@22.6,70
  Bottom Layer w0.7: D19.3@2.8,93.9 3.6,94.7 8.3,94.7 9.6,96 RL1.1@9.6,98.2
BELL_1: Q4.1 X3.5 | length 6
  Bottom Layer w0.5: X3.5@40,96.975 41.875,98.85 Q4.1@45.2,98.85
BOOT_1: R34.1 U2.44 | length 1.1
  Bottom Layer w0.2: U2.44@14.25,8.15 R34.1@15.35,8.15
BUZZER_1: Q3.2 R42.1 U2.21 | length 28
  Bottom Layer w0.2: Q3.2@4.65,33.25 4.4,33.25 3.9,33.75 R42.1@3.3,33.75 2.8,33.25 2.8,15.8 6.848,11.752 6.848,10.348 6.65,10.15 U2.21@5.75,10.15
CAP_GROUP1_1: C12.2 U2.13 | length 1.5
  Bottom Layer w0.152: C12.2@4.34,6.3 C12.2@4.49,6.15
  Bottom Layer w0.2: C12.2@4.49,6.15 U2.13@5.75,6.15
CAP_GROUP2_1: C13.2 U2.14 | length 1.7
  Bottom Layer w0.2: C13.2@4.34,7.3 4.99,6.65 U2.14@5.75,6.65
CAP_GROUP3_1: C14.2 U2.19 | length 1.4
  Bottom Layer w0.2: C14.2@4.34,9.15 U2.19@5.75,9.15
CAP_GROUP4_1: C15.2 U2.32 | length 2.7
  Bottom Layer w0.2: U2.32@10.75,13.15 10.698,13.202 10.698,14.798 10.95,15.05 C15.2@11.61,15.05
CAP_GROUP5_1: C16.2 U2.39 | length 1.4
  Bottom Layer w0.2: U2.39@14.25,10.65 C16.2@15.66,10.65
CAP_GROUP6_1: C17.2 U2.22 | length 1.4
  Bottom Layer w0.2: C17.2@4.34,10.65 U2.22@5.75,10.65
CAPKEY1_1: K1.1 R6.2 | length 1.7
  Bottom Layer w0.152: R6.2@9.3,71.25 v3(9.3,73)
CAPKEY2_1: K2.1 R16.2 | length 1.8
  Bottom Layer w0.152: v3(30.336,74.464) R16.2@31.582,73.218
CAPKEY3_1: K3.1 R17.2 | length 2.2
  Bottom Layer w0.152: R17.2@42.718,71.418 v3(44.3,73)
CAPKEY4_1: K4.1 R18.2 | length 1.8
  Bottom Layer w0.152: v3(12.836,56.964) R18.2@14.082,55.718
CAPKEY5_1: K5.1 R19.2 | length 1.8
  Bottom Layer w0.152: R19.2@22.018,55.718 R19.2@22.118,55.818 v3(23.264,56.964)
CAPKEY6_1: K6.1 R20.2 | length 1.8
  Bottom Layer w0.152: R20.2@39.518,55.718 v3(40.764,56.964)
CAPKEY7_1: K7.1 R21.2 | length 1.8
  Bottom Layer w0.152: v3(12.836,39.464) R21.2@14.082,38.218
CAPKEY8_1: K8.1 R22.2 | length 1.8
  Bottom Layer w0.152: R22.2@22.018,38.218 R22.2@22.168,38.368 v3(23.264,39.464)
CAPKEY9_1: K9.1 R30.2 | length 1.8
  Bottom Layer w0.152: R30.2@39.518,38.218 v3(40.764,39.464)
CAPKEY10_1: K10.1 R31.2 | length 1.5
  Bottom Layer w0.2: R31.2@9.3,18.95 v3(9.3,20.5)
CAPKEY11_1: K11.1 R32.2 | length 1.8
  Bottom Layer w0.152: R32.2@22.018,20.718 R32.2@22.168,20.868 v3(23.264,21.964)
  Bottom Layer w0.2: v3(23.264,21.964) v3@23.314,22.014
CAPKEY12_1: K12.1 R33.2 | length 1.8
  Bottom Layer w0.152: R33.2@39.518,30.282 v3(40.764,29.036)
CAPKEY13_1: K13.1 R35.2 | length 1.9
  Bottom Layer w0.152: R35.2@20.15,10 20.154,10.004 v3(22.031,10.004)
CAPSHIELD_1: R36.2 | length 40.2
  Bottom Layer w0.152: R36.2@6.6,16.05 v2(6.6,16.95)
  Bottom Layer w0.8: v2(3.9,17.028) v2(3.9,19.35) ; v2(5.3,17.021) v2(5.3,19.343) ; v2(18.502,21.95) v2(20.252,21.95) ; v2(18.502,34.15) v2(20.252,34.15) ; v2(18.502,37.5) v2(20.252,37.5) ; v2(18.502,46.85) v2(20.252,46.85) ; v2(18.502,51.55) v2(20.252,51.55) ; v2(18.502,56.2) v2(20.252,56.2) ; v2(22.4,31.575) v2(22.4,33.325) ; v2(24.5,67.35) v2(24.5,70.75) ; v2(27.45,70.75) 27.45,68.85 v2(28.9,67.4) ; v2(40.4,31.65) v2(40.4,34.9) ; v2(40.45,66.65) v2(40.45,70.75) ; v2(48,66.663) 49.313,66.663 49.95,67.3 v2(49.95,70.75) ; v2(50.55,34.85) 50.55,33.9 v2(51.35,33.1)
COM_1: RL1.2 X3.3 | length 35
  Top Layer w0.7: RL1.2@7.6,92.2 8.2,92.2 9.7,90.7 14.4,90.7 16.054,92.354 25.318,92.354 25.326,92.346 26.074,92.346 26.082,92.354 35.754,92.354 v4(37,93.6)
  Bottom Layer w0.7: X3.3@36,96.975 36,94.6 v4(37,93.6)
